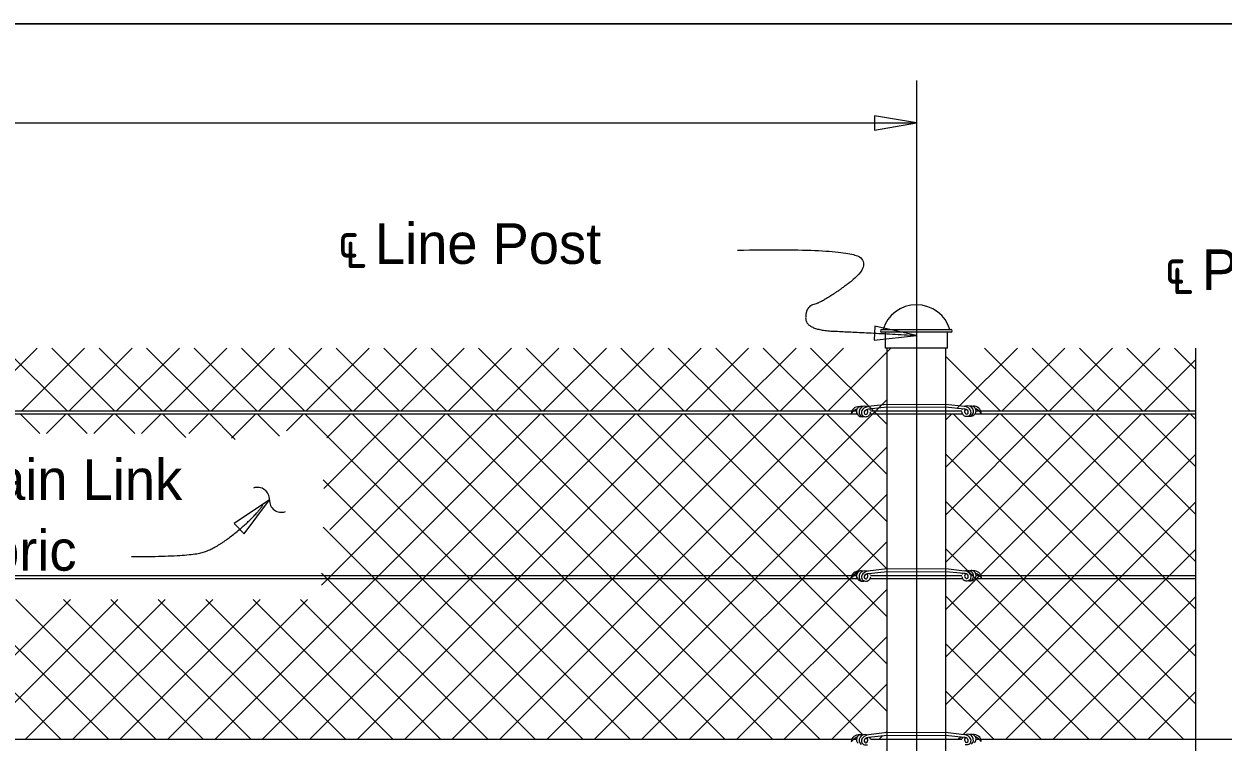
# Model space of a CAD drawing. Extents: x 0 to 41.2, y 0 to 26.
# Drawn here: x 17.77 to 23.73, y 22.39 to 25.96 of the extents above; entities that cross this region are included whole.
import ezdxf

# ---------------------------------------------------------------- set-up
doc = ezdxf.new("R2010")
doc.units = 0
for name, color, linetype in [('ActivePts-ConstElements', 7, 'Continuous'), ('CL_Major', 7, 'Continuous'), ('Dimension', 7, 'Continuous'), ('Miscellaneous', 7, 'Continuous'), ('Miscellaneous1', 7, 'Continuous'), ('SteelMisc', 7, 'Continuous'), ('SteelMisc_h', 7, 'Continuous'), ('TextStructures', 7, 'Continuous')]:
    doc.layers.add(name, color=color, linetype=linetype)

msp = doc.modelspace()

# ---------------------------------------------------------------- linework, layer by layer
at = {"layer": 'ActivePts-ConstElements'}
msp.add_lwpolyline([(0, 0), (41.2106, 0), (41.2106, 25.96), (0, 25.96)], close=True, dxfattribs=at)
at = {"layer": 'CL_Major'}
msp.add_line((22.2062, 25.6784), (22.2062, 14.8312), dxfattribs=at)
at = {"layer": 'Dimension'}
msp.add_line((2.2062, 25.4682), (22.2062, 25.4682), dxfattribs=at)
for points in [[(22.2062, 25.4682), (21.998, 25.5035), (21.998, 25.4329)], [(22.2064, 24.4121), (22.0003, 24.4587), (21.9965, 24.3883)], [(18.9917, 23.5942), (18.8164, 23.4764), (18.865, 23.4252)]]:
    msp.add_lwpolyline(points, close=True, dxfattribs=at)
msp.add_lwpolyline([(23.5932, 24.349), (23.5932, 21.1819), (23.6966, 21.1819), (23.5932, 21.1369), (23.4899, 21.0919), (23.5932, 21.0919), (23.5932, 20.1983)], dxfattribs=at)
for centre, start, end in [((18.9315, 23.597), 357.71778, 109.44499), ((19.0506, 23.5923), 177.71778, 289.44499)]:
    msp.add_arc(centre, 0.0596, start, end, dxfattribs=at)
for points in [[(21.3168, 24.8359), (21.8626, 24.8457), (21.985, 24.7568), (21.7408, 24.5755), (21.6559, 24.5571), (21.6559, 24.4393), (21.934, 24.427), (22.2063, 24.4121)], [(18.3063, 23.3125), (18.5965, 23.3125), (18.7331, 23.3573), (18.9201, 23.5109), (18.9585, 23.5685)]]:
    msp.add_open_spline(points, degree=2, dxfattribs=at)
at = {"layer": 'Miscellaneous'}
for p, q in [((17.5245, 24.0365), (17.837, 24.349)), ((17.6736, 24.349), (17.9861, 24.0365)), ((17.7602, 24.0365), (18.0727, 24.349)), ((17.9093, 24.349), (18.2218, 24.0365)), ((17.9959, 24.0365), (18.3084, 24.349)), ((18.145, 24.349), (18.4575, 24.0365)), ((18.2316, 24.0365), (18.5441, 24.349)), ((18.3807, 24.349), (18.6932, 24.0365)), ((18.4673, 24.0365), (18.7799, 24.349)), ((18.6164, 24.349), (18.9289, 24.0365)), ((18.703, 24.0365), (19.0156, 24.349)), ((18.8521, 24.349), (19.1646, 24.0365)), ((18.9387, 24.0365), (19.2513, 24.349)), ((19.0878, 24.349), (19.4003, 24.0365)), ((19.1744, 24.0365), (19.487, 24.349)), ((19.3235, 24.349), (19.636, 24.0365)), ((19.4101, 24.0365), (19.7227, 24.349)), ((19.5592, 24.349), (19.8717, 24.0365)), ((19.6458, 24.0365), (19.9584, 24.349)), ((19.7949, 24.349), (20.1074, 24.0365)), ((19.8815, 24.0365), (20.1941, 24.349)), ((20.0306, 24.349), (20.3431, 24.0365)), ((20.1172, 24.0365), (20.4298, 24.349)), ((20.2663, 24.349), (20.5788, 24.0365)), ((20.3529, 24.0365), (20.6655, 24.349)), ((20.502, 24.349), (20.8145, 24.0365)), ((20.5886, 24.0365), (20.9012, 24.349)), ((20.7377, 24.349), (21.0502, 24.0365)), ((20.8243, 24.0365), (21.1369, 24.349)), ((20.9734, 24.349), (21.2859, 24.0365)), ((21.06, 24.0365), (21.3726, 24.349)), ((21.2091, 24.349), (21.5216, 24.0365)), ((21.2957, 24.0365), (21.6083, 24.349)), ((21.4448, 24.349), (21.7573, 24.0365)), ((21.5314, 24.0365), (21.844, 24.349)), ((21.6805, 24.349), (22.0604, 23.9692)), ((21.7671, 24.0365), (22.0797, 24.349)), ((22.4077, 24.048), (22.7088, 24.349)), ((22.5453, 24.349), (22.8578, 24.0365)), ((22.6319, 24.0365), (22.9445, 24.349)), ((22.781, 24.349), (23.0935, 24.0365)), ((22.8676, 24.0365), (23.1802, 24.349)), ((23.0167, 24.349), (23.3292, 24.0365)), ((23.1033, 24.0365), (23.4159, 24.349)), ((23.2524, 24.349), (23.5649, 24.0365)), ((23.4881, 24.349), (23.5932, 24.2439)), ((22.3521, 24.3066), (22.6221, 24.0365)), ((23.339, 24.0365), (23.5932, 24.2907)), ((20.3711, 22.4048), (22.0604, 24.094)), ((22.5076, 24.0365), (22.5121, 24.041)), ((17.7524, 24.0218), (17.85, 23.9241)), ((17.8835, 23.9241), (17.9812, 24.0218)), ((17.9881, 24.0218), (18.0857, 23.9241)), ((18.1192, 23.9241), (18.2169, 24.0218)), ((18.2238, 24.0218), (18.3214, 23.9241)), ((18.3549, 23.9241), (18.4526, 24.0218)), ((18.4595, 24.0218), (18.5763, 23.9049)), ((18.5906, 23.9241), (18.6883, 24.0218)), ((18.6952, 24.0218), (18.8216, 23.8953)), ((18.8028, 23.9006), (18.924, 24.0218)), ((18.9309, 24.0218), (19.0418, 23.9108)), ((18.9569, 22.4048), (20.5739, 24.0218)), ((19.0752, 23.9373), (19.1597, 24.0218)), ((19.1666, 24.0218), (20.7836, 22.4048)), ((19.1926, 22.4048), (20.8096, 24.0218)), ((19.2506, 23.1699), (20.1025, 24.0218)), ((19.2506, 22.9342), (20.3382, 24.0218)), ((19.2609, 23.6515), (19.6311, 24.0218)), ((19.2761, 23.9025), (19.3954, 24.0218)), ((19.2906, 23.4456), (19.8668, 24.0218)), ((19.4023, 24.0218), (21.0193, 22.4048)), ((19.4283, 22.4048), (21.0453, 24.0218)), ((19.638, 24.0218), (21.255, 22.4048)), ((19.664, 22.4048), (21.281, 24.0218)), ((19.8737, 24.0218), (21.4907, 22.4048)), ((19.8997, 22.4048), (21.5167, 24.0218)), ((20.1094, 24.0218), (21.7264, 22.4048)), ((20.1354, 22.4048), (21.7524, 24.0218)), ((20.3451, 24.0218), (21.9407, 22.4262)), ((20.5808, 24.0218), (22.0604, 22.5421)), ((20.8165, 24.0218), (22.0604, 22.7779)), ((21.0522, 24.0218), (22.0604, 23.0136)), ((21.2879, 24.0218), (22.0604, 23.2493)), ((21.5236, 24.0218), (22.0604, 23.485)), ((21.7593, 24.0218), (22.0604, 23.7207)), ((22.3521, 22.8138), (23.56, 24.0218)), ((22.3521, 23.0495), (23.3243, 24.0218)), ((22.3521, 23.2852), (23.0886, 24.0218)), ((22.3521, 23.5209), (22.8529, 24.0218)), ((22.3521, 23.7566), (22.6172, 24.0218)), ((22.3521, 23.9923), (22.3815, 24.0218)), ((22.3884, 24.0218), (23.5931, 22.817)), ((22.6241, 24.0218), (23.5931, 23.0527)), ((22.8598, 24.0218), (23.5931, 23.2884)), ((23.0955, 24.0218), (23.5931, 23.5241)), ((23.3312, 24.0218), (23.5931, 23.7598)), ((23.5669, 24.0218), (23.5931, 23.9955)), ((20.6068, 22.4048), (22.0604, 23.8583)), ((22.3521, 23.8224), (23.5931, 22.5813)), ((22.3521, 22.5781), (23.5932, 23.8193)), ((19.2586, 23.6941), (20.5479, 22.4048)), ((20.8425, 22.4048), (22.0604, 23.6226)), ((22.3521, 23.5867), (23.534, 22.4048)), ((22.4378, 22.4282), (23.5932, 23.5836)), ((19.2574, 23.4595), (20.3122, 22.4048)), ((21.0782, 22.4048), (22.0604, 23.3869)), ((22.3521, 23.351), (23.2983, 22.4048)), ((22.6501, 22.4048), (23.5932, 23.3479)), ((19.2506, 23.2306), (20.0765, 22.4048)), ((22.5078, 23.219), (22.5123, 23.2235)), ((21.3139, 22.4048), (22.0604, 23.1512)), ((17.26, 23.0999), (17.9551, 22.4048)), ((17.307, 22.4048), (18.0021, 23.0999)), ((17.4957, 23.0999), (18.1908, 22.4048)), ((17.5427, 22.4048), (18.2378, 23.0999)), ((17.7314, 23.0999), (18.4265, 22.4048)), ((17.7784, 22.4048), (18.4735, 23.0999)), ((17.9671, 23.0999), (18.6623, 22.4048)), ((18.0141, 22.4048), (18.7092, 23.0999)), ((18.2028, 23.0999), (18.898, 22.4048)), ((18.2498, 22.4048), (18.9449, 23.0999)), ((18.4385, 23.0999), (19.1337, 22.4048)), ((18.4855, 22.4048), (19.1806, 23.0999)), ((18.6742, 23.0999), (19.3694, 22.4048)), ((18.7212, 22.4048), (19.4163, 23.0999)), ((18.9099, 23.0999), (19.6051, 22.4048)), ((19.1456, 23.0999), (19.8408, 22.4048)), ((22.3521, 23.1153), (23.0626, 22.4048)), ((22.8858, 22.4048), (23.5932, 23.1122)), ((21.5496, 22.4048), (22.0604, 22.9155)), ((22.3521, 22.8796), (22.8269, 22.4048)), ((23.1215, 22.4048), (23.5931, 22.8764)), ((21.7853, 22.4048), (22.0604, 22.6798)), ((22.3521, 22.6439), (22.5912, 22.4048)), ((23.3572, 22.4048), (23.5931, 22.6407)), ((22.0527, 22.4364), (22.0604, 22.4441)), ((21.9567, 22.4102), (21.9654, 22.4015)), ((22.021, 22.4048), (22.0367, 22.4204)), ((22.3521, 22.4082), (22.3555, 22.4048)), ((22.4144, 22.4048), (22.4264, 22.4168)), ((23.5929, 22.4048), (23.5932, 22.4051))]:
    msp.add_line(p, q, dxfattribs=at)
at = {"layer": 'Miscellaneous1'}
msp.add_lwpolyline([(0, 25.96), (41.2106, 25.96), (41.2106, 0), (0, 0)], close=True, dxfattribs=at)
at = {"layer": 'SteelMisc'}
for p, q in [((22.0339, 24.441), (22.3785, 24.441)), ((22.3785, 24.4288), (22.0339, 24.4288)), ((22.0521, 24.349), (22.0521, 24.4288)), ((22.3602, 24.349), (22.3602, 24.4288)), ((22.3602, 24.349), (22.0521, 24.349)), ((22.0604, 17.8646), (22.0604, 24.349)), ((22.3521, 17.8646), (22.3521, 24.349)), ((12.5051, 24.0365), (21.8852, 24.0365)), ((21.8951, 24.0365), (21.9083, 24.0365)), ((22.0603, 24.0691), (21.9655, 24.058)), ((22.0603, 24.0546), (21.9677, 24.0451)), ((21.9782, 24.0365), (22.0603, 24.0365)), ((22.0603, 24.0691), (22.3515, 24.0708)), ((22.0603, 24.0546), (22.3515, 24.0563)), ((22.3515, 24.0708), (22.4458, 24.0597)), ((22.3515, 24.0563), (22.4437, 24.0469)), ((22.352, 24.0365), (22.4324, 24.0365)), ((22.5028, 24.0365), (22.518, 24.0365)), ((22.5265, 24.0365), (23.5931, 24.0365)), ((12.5051, 24.0218), (21.9118, 24.0218)), ((21.9767, 24.0218), (22.0603, 24.0218)), ((22.352, 24.0218), (22.4351, 24.0218)), ((22.4978, 24.0218), (23.5931, 24.0218)), ((12.5053, 23.219), (21.8854, 23.219)), ((12.5053, 23.2043), (21.912, 23.2043)), ((21.8953, 23.219), (21.9084, 23.219)), ((22.0605, 23.2516), (21.9656, 23.2405)), ((22.0605, 23.2371), (21.9679, 23.2276)), ((21.9769, 23.2043), (22.0605, 23.2043)), ((21.9783, 23.219), (22.0605, 23.219)), ((22.0605, 23.2516), (22.3517, 23.2533)), ((22.0605, 23.2371), (22.3517, 23.2388)), ((22.3517, 23.2533), (22.446, 23.2422)), ((22.3517, 23.2388), (22.4438, 23.2294)), ((22.3522, 23.219), (22.4326, 23.219)), ((22.3522, 23.2043), (22.4352, 23.2043)), ((22.498, 23.2043), (23.5933, 23.2043)), ((22.5029, 23.219), (22.5182, 23.219)), ((22.5266, 23.219), (23.5933, 23.219)), ((22.0603, 22.4374), (21.9675, 22.4257)), ((22.0603, 22.4229), (21.9675, 22.4132)), ((22.0603, 22.4374), (22.3515, 22.4391)), ((22.0603, 22.4229), (22.3515, 22.4245)), ((22.3515, 22.4391), (22.4435, 22.4275)), ((22.3515, 22.4245), (22.4434, 22.415)), ((12.5265, 22.4048), (21.8852, 22.4048)), ((21.8951, 22.4048), (21.9083, 22.4048)), ((21.9782, 22.4048), (22.0603, 22.4048)), ((22.352, 22.4048), (22.4324, 22.4048)), ((22.5028, 22.4048), (22.518, 22.4048)), ((22.5265, 22.4048), (25.929, 22.4048))]:
    msp.add_line(p, q, dxfattribs=at)
for centre, start, end in [((22.034, 24.4347), 91.1647, 268.8353), ((22.3783, 24.4347), 271.1647, 88.8353)]:
    msp.add_arc(centre, 0.00613, start, end, dxfattribs=at)
for centre, major_axis, ratio, start_param, end_param in [((22.2068, 24.4), (0.1711, 0), 0.957868, 0.252602, 2.888574), ((21.9194, 24.0222), (0.0373, 0), 0.957868, 1.486836, 3.108042), ((21.9405, 23.9825), (-0.0724, 0), 0.957868, 5.162149, 5.652106), ((21.9331, 24.0342), (-0.0249, 0), 0.957868, 6.009018, 7.089857), ((21.9319, 24.0367), (0.023, 0), 0.957868, 1.29026, 2.970541), ((21.9507, 24.0313), (0.0295, 0), 0.957868, 1.220941, 4.039556), ((21.9641, 24.0331), (-0.0303, -0.0108), 0.724765, 4.35367, 6.324556), ((21.9608, 24.029), (-0.0139, 0), 0.957868, 5.22362, 6.905413), ((21.9692, 24.0202), (-0.0259, 0), 0.957868, 4.777514, 5.62749), ((21.9535, 24.0325), (0.0119, 0), 0.957868, 5.725876, 7.416677), ((21.9537, 24.0312), (0.0251, 0), 0.957868, 0.407687, 0.609214), ((22.4572, 24.033), (-0.0251, 0), 0.957868, 5.673972, 5.875498), ((22.4417, 24.022), (0.0259, 0), 0.957868, 0.655696, 1.505671), ((22.4468, 24.0349), (0.0303, -0.0108), 0.724765, 6.241815, 8.212701), ((22.4574, 24.0342), (-0.0119, 0), 0.957868, 5.149694, 6.840495), ((22.4603, 24.0331), (-0.0295, 0), 0.957868, 2.243629, 5.062245), ((22.4501, 24.0308), (0.0139, 0), 0.957868, 5.660958, 7.342751), ((22.479, 24.0385), (-0.023, 0), 0.957868, 3.312645, 4.992926), ((22.4915, 24.024), (-0.0373, 0), 0.957868, 3.175144, 4.79635), ((22.4779, 24.036), (0.0249, 0), 0.957868, 5.476514, 6.557353), ((22.4704, 23.9843), (0.0724, 0), 0.957868, 0.631079, 1.121037), ((21.9344, 24.0302), (0.0231, 0), 0.957868, 3.779554, 4.879821), ((21.9405, 24.0245), (0.0206, -0.0021), 0.798607, 4.32653, 5.220153), ((21.954, 24.0245), (0.0206, -0.0021), 0.798607, 3.333154, 5.220153), ((21.9552, 24.0267), (-0.00795, 0), 0.957868, 6.140374, 9.314262), ((21.9466, 24.0433), (0.0391, 0), 0.957868, 5.082588, 5.41974), ((21.9535, 24.0325), (0.0119, 0), 0.957868, 5.639684, 5.723117), ((21.9537, 24.0312), (0.0251, 0), 0.957868, 5.531357, 6.227833), ((22.4572, 24.033), (-0.0251, 0), 0.957868, 0.055352, 0.751829), ((22.4643, 24.045), (-0.0391, 0), 0.957868, 0.863445, 1.200597), ((22.4574, 24.0342), (-0.0119, 0), 0.957868, 0.560069, 0.643501), ((22.4558, 24.0284), (0.00795, 0), 0.957868, 3.252108, 6.425997), ((22.4569, 24.0263), (-0.0206, -0.0021), 0.798607, 1.063032, 2.950031), ((22.4704, 24.0263), (-0.0206, -0.0021), 0.798607, 1.063032, 1.956656), ((22.4765, 24.032), (-0.0231, 0), 0.957868, 1.403365, 2.503632), ((21.9196, 23.2048), (0.0373, 0), 0.957868, 1.486836, 3.108042), ((21.9407, 23.1651), (-0.0724, 0), 0.957868, 5.162149, 5.652106), ((21.9332, 23.2167), (-0.0249, 0), 0.957868, 6.009018, 7.089857), ((21.9321, 23.2192), (0.023, 0), 0.957868, 1.29026, 2.970541), ((21.9346, 23.2127), (0.0231, 0), 0.957868, 3.779554, 4.879821), ((21.9508, 23.2139), (0.0295, 0), 0.957868, 1.220941, 4.039556), ((21.9643, 23.2157), (-0.0303, -0.0108), 0.724765, 4.35367, 6.324556), ((21.9542, 23.207), (0.0206, -0.0021), 0.798607, 3.333154, 5.220153), ((21.961, 23.2116), (-0.0139, 0), 0.957868, 5.22362, 6.905413), ((21.9553, 23.2092), (-0.00795, 0), 0.957868, 6.140374, 9.314262), ((21.9694, 23.2027), (-0.0259, 0), 0.957868, 4.777514, 5.62749), ((21.9536, 23.215), (0.0119, 0), 0.957868, 5.725876, 7.416677), ((21.9536, 23.215), (0.0119, 0), 0.957868, 5.639684, 5.723117), ((21.9539, 23.2138), (0.0251, 0), 0.957868, 5.531357, 6.227833), ((21.9539, 23.2138), (0.0251, 0), 0.957868, 0.407687, 0.609214), ((22.4574, 23.2155), (-0.0251, 0), 0.957868, 0.055352, 0.751829), ((22.4574, 23.2155), (-0.0251, 0), 0.957868, 5.673972, 5.875498), ((22.4644, 23.2276), (-0.0391, 0), 0.957868, 0.863445, 1.200597), ((22.4469, 23.2174), (0.0303, -0.0108), 0.724765, 6.241815, 8.212701), ((22.4419, 23.2045), (0.0259, 0), 0.957868, 0.655696, 1.505671), ((22.4576, 23.2168), (-0.0119, 0), 0.957868, 5.149694, 6.840495), ((22.4576, 23.2168), (-0.0119, 0), 0.957868, 0.560069, 0.643501), ((22.4559, 23.211), (0.00795, 0), 0.957868, 3.252108, 6.425997), ((22.4571, 23.2088), (-0.0206, -0.0021), 0.798607, 1.063032, 2.950031), ((22.4604, 23.2156), (-0.0295, 0), 0.957868, 2.243629, 5.062245), ((22.4503, 23.2134), (0.0139, 0), 0.957868, 5.660958, 7.342751), ((22.4792, 23.221), (-0.023, 0), 0.957868, 3.312645, 4.992926), ((22.4766, 23.2145), (-0.0231, 0), 0.957868, 1.403365, 2.503632), ((22.4917, 23.2065), (-0.0373, 0), 0.957868, 3.175144, 4.79635), ((22.478, 23.2185), (0.0249, 0), 0.957868, 5.476514, 6.557353), ((22.4705, 23.1668), (0.0724, 0), 0.957868, 0.631079, 1.121037), ((21.9407, 23.207), (0.0206, -0.0021), 0.798607, 4.32653, 5.220153), ((21.9468, 23.2258), (0.0391, 0), 0.957868, 5.082588, 5.41974), ((22.4705, 23.2088), (-0.0206, -0.0021), 0.798607, 1.063032, 1.956656), ((21.9194, 22.3905), (0.0373, 0), 0.957868, 1.427863, 3.108042), ((21.9319, 22.405), (0.023, 0), 0.957868, 1.234085, 2.861055), ((21.9507, 22.3996), (0.0295, 0), 0.957868, 1.132635, 3.996184), ((21.9641, 22.4014), (-0.0303, -0.0108), 0.724765, 4.35367, 6.224248), ((22.4468, 22.4032), (0.0303, -0.0108), 0.724765, 0.058937, 1.929515), ((22.4603, 22.4014), (-0.0295, 0), 0.957868, 2.287002, 5.15055), ((22.479, 22.4067), (-0.023, 0), 0.957868, 3.422131, 5.0491), ((22.4915, 22.3923), (-0.0373, 0), 0.957868, 3.175144, 4.855322), ((21.9405, 22.3508), (-0.0724, 0), 0.957868, 5.133134, 5.652106), ((21.9331, 22.4025), (-0.0249, 0), 0.957868, 5.913851, 7.104804), ((21.954, 22.3928), (0.0206, -0.0021), 0.798607, 3.319436, 5.220153), ((21.9608, 22.3973), (-0.0139, 0), 0.957868, 5.822914, 6.485782), ((21.9552, 22.3949), (-0.00795, 0), 0.957868, 0.039428, 2.999692), ((21.9692, 22.3885), (-0.0259, 0), 0.957868, 4.777514, 5.646371), ((21.9535, 22.4007), (0.0119, 0), 0.957868, 5.725876, 7.416677), ((21.9535, 22.4007), (0.0119, 0), 0.957868, 5.639684, 5.723117), ((21.9537, 22.3995), (0.0251, 0), 0.957868, 0.221743, 0.642584), ((22.4572, 22.4013), (-0.0251, 0), 0.957868, 5.640694, 6.136824), ((22.4417, 22.3902), (0.0259, 0), 0.957868, 0.636815, 1.505671), ((22.4574, 22.4025), (-0.0119, 0), 0.957868, 5.149694, 6.840495), ((22.4574, 22.4025), (-0.0119, 0), 0.957868, 0.560069, 0.643501), ((22.4558, 22.3967), (0.00795, 0), 0.957868, 3.283494, 6.243757), ((22.4569, 22.3945), (-0.0206, -0.0021), 0.798607, 1.063032, 2.96375), ((22.4501, 22.3991), (0.0139, 0), 0.957868, 6.080589, 6.743456), ((22.4779, 22.4042), (0.0249, 0), 0.957868, 5.476514, 6.65252), ((22.4704, 22.3526), (0.0724, 0), 0.957868, 0.631079, 1.150052)]:
    msp.add_ellipse(centre, major_axis=major_axis, ratio=ratio, start_param=start_param, end_param=end_param, dxfattribs=at)
at = {"layer": 'SteelMisc_h'}
for p, q in [((22.0603, 24.0365), (22.352, 24.0365)), ((22.0603, 24.0218), (22.352, 24.0218)), ((22.0605, 23.219), (22.3522, 23.219)), ((22.0605, 23.2043), (22.3522, 23.2043)), ((22.0603, 22.4048), (22.352, 22.4048))]:
    msp.add_line(p, q, dxfattribs=at)

# ---------------------------------------------------------------- texts
at = {"layer": 'Dimension'}
for s, p in [('Chain Link ', (17.2835, 23.5945)), ('Fabric ', (17.2835, 23.2425))]:
    msp.add_text(s, height=0.2016, dxfattribs=at).set_placement(p)
at = {"layer": 'TextStructures'}
for s, p in [('℄ Line Post', (19.3314, 24.7677)), ('℄ Pull Post', (23.4401, 24.6377))]:
    msp.add_text(s, height=0.2016, dxfattribs=at).set_placement(p)

doc.saveas('drawing.dxf')
